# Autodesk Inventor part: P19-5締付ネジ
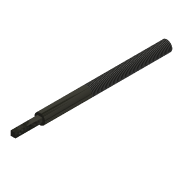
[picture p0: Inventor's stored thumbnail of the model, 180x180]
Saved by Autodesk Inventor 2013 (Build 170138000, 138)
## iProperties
Created: 2008-07
Part Number: P19-5締付ネジ
Document SubType Name: Modeling
Designer: y-shimohigashi
Density: 1 g/cm^3
Stock Number: P19-5締付ネジ
Material: 一般
Author: y-shimohigashi
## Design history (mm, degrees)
sketch "スケッチ2"
  geometry: C1 r 8 at (0, 0); 1 further point
  constraints: 1 centre point, 1 coincident
  dimensions: "d0" = 16 diameter of C1
extrude "押し出し1" new body sketch "スケッチ2" distance "d1" = 190; taper "d2" = 0 deg
sketch "スケッチ3"
  geometry: L1 (3.536, 3.536)-(-3.536, 3.536); L2 (-3.536, 3.536)-(-3.536, -3.536); L3 (-3.536, -3.536)-(3.536, -3.536); L4 (3.536, -3.536)-(3.536, 3.536); L5 (-3.536, 3.536)-(3.536, -3.536); 2 further points
  constraints: 10 end point, 2 parallel, 2 perpendicular, 1 coincident, 1 horizontal, 1 midpoint
  dimensions: "d3" = 10 distance of L1.end L3.end
extrude "押し出し2" join sketch "スケッチ3" distance "d4" = 40; taper "d5" = 0 deg
sketch "スケッチ4"
  geometry: L1 (-86, 0)-(236, 0) reference; L2 (-40, -3.536)-(-40, 3.536) reference; 1 further point
  constraints: 1 point on line
  dimensions: "d6" = 7 distance from line of point (-33, 0) L2
hole "穴1" sketch "スケッチ4" diameter "d7" = 2.459; stored, may be unused: countersink angle "d11" = 90 deg, drill point angle "d13" = 118 deg; dims "d8" = 6, "d9" = 4, "d10" = 2, "d12" = 8
hole "穴2" sketch "スケッチ4" diameter "d14" = 2.459; stored, may be unused: countersink angle "d18" = 90 deg, drill point angle "d20" = 118 deg; dims "d15" = 6, "d16" = 4, "d17" = 2, "d19" = 8
feature "ねじ1" dims "d21" = 120, "d22" = 0
node "ソリッド1"
node "ソリッド ボディ"
node "サーフェス ボディ"
